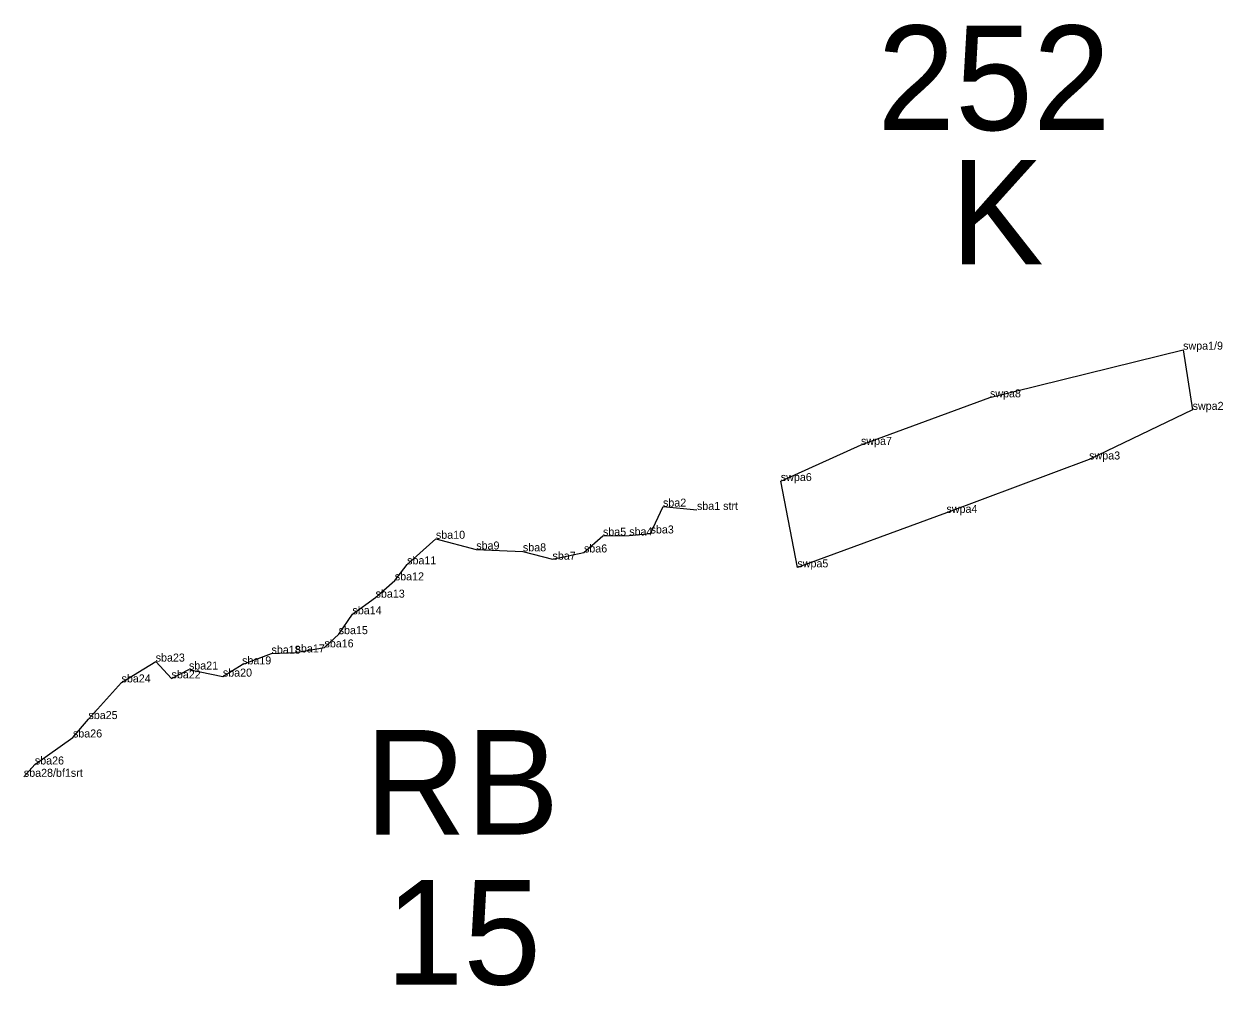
# Model space of a CAD drawing. Extents: x 2072529 to 2268796, y 436423 to 470406.
# Drawn here: x 2212483 to 2213233, y 440541 to 441142 of the extents above; entities that cross this region are included whole.
import ezdxf

# ---------------------------------------------------------------- set-up
doc = ezdxf.new("R2010")
doc.units = 0
for name, color, linetype in [('Default', 7, 'Continuous'), ('Exist Hydro Jurisdictional Stream or Body of Water NEU Mitigable', 7, 'Continuous'), ('Exist Hydro Jurisdictional Stream or Body of Water NEU Mitigable Cogo Comment', 7, 'Continuous'), ('Old_Level_20', 7, 'Continuous')]:
    doc.layers.add(name, color=color, linetype=linetype)

msp = doc.modelspace()

# ---------------------------------------------------------------- linework, layer by layer
at = {"layer": 'Exist Hydro Jurisdictional Stream or Body of Water NEU Mitigable'}
msp.add_lwpolyline([(2213207.67, 440938.67), (2213213.62, 440901.09), (2213148.99, 440870.07), (2213059.83, 440836.73), (2212966.67, 440802.64), (2212956.32, 440856.6), (2213006.42, 440879.17), (2213087, 440908.88)], close=True, dxfattribs=at)
msp.add_lwpolyline([(2212483.34, 440671.77), (2212490.22, 440679.47), (2212514.04, 440696.37), (2212523.7, 440707.85), (2212544.37, 440730.76), (2212565.72, 440743.79), (2212575.62, 440733.28), (2212586.51, 440738.8), (2212607.7, 440734.4), (2212619.7, 440742.03), (2212638.08, 440748.74), (2212653.12, 440749.49), (2212671.17, 440752.66), (2212680.06, 440760.92), (2212688.66, 440773.35), (2212703.11, 440783.75), (2212715.14, 440794.53), (2212722.83, 440804.55), (2212740.82, 440820.52), (2212766.02, 440813.82), (2212795.17, 440812.67), (2212813.67, 440807.74), (2212833.33, 440811.97), (2212845.18, 440822.43), (2212861.6, 440822.58), (2212874.93, 440823.84), (2212882.7, 440840.61), (2212903.91, 440838.55)], dxfattribs=at)
at = {"layer": 'Old_Level_20'}
for p, q in [((2213207.67, 440938.67), (2213207.67, 440938.67)), ((2213087, 440908.88), (2213087, 440908.88)), ((2213213.62, 440901.09), (2213213.62, 440901.09)), ((2213006.42, 440879.17), (2213006.42, 440879.17)), ((2213148.99, 440870.07), (2213148.99, 440870.07)), ((2212956.32, 440856.6), (2212956.32, 440856.6)), ((2212882.7, 440840.61), (2212882.7, 440840.61)), ((2212903.91, 440838.55), (2212903.91, 440838.55)), ((2213059.83, 440836.73), (2213059.83, 440836.73)), ((2212874.93, 440823.84), (2212874.93, 440823.84)), ((2212740.82, 440820.52), (2212740.82, 440820.52)), ((2212845.18, 440822.43), (2212845.18, 440822.43)), ((2212861.6, 440822.58), (2212861.6, 440822.58)), ((2212766.02, 440813.82), (2212766.02, 440813.82)), ((2212795.17, 440812.67), (2212795.17, 440812.67)), ((2212833.33, 440811.97), (2212833.33, 440811.97)), ((2212722.83, 440804.55), (2212722.83, 440804.55)), ((2212813.67, 440807.74), (2212813.67, 440807.74)), ((2212966.67, 440802.64), (2212966.67, 440802.64)), ((2212715.14, 440794.53), (2212715.14, 440794.53)), ((2212703.11, 440783.75), (2212703.11, 440783.75)), ((2212688.66, 440773.35), (2212688.66, 440773.35)), ((2212680.06, 440760.92), (2212680.06, 440760.92)), ((2212638.08, 440748.74), (2212638.08, 440748.74)), ((2212653.12, 440749.49), (2212653.12, 440749.49)), ((2212671.17, 440752.66), (2212671.17, 440752.66)), ((2212565.72, 440743.79), (2212565.72, 440743.79)), ((2212619.7, 440742.03), (2212619.7, 440742.03)), ((2212575.62, 440733.28), (2212575.62, 440733.28)), ((2212586.51, 440738.8), (2212586.51, 440738.8)), ((2212607.7, 440734.4), (2212607.7, 440734.4)), ((2212544.37, 440730.76), (2212544.37, 440730.76)), ((2212523.7, 440707.85), (2212523.7, 440707.85)), ((2212514.04, 440696.37), (2212514.04, 440696.37)), ((2212490.22, 440679.47), (2212490.22, 440679.47))]:
    msp.add_line(p, q, dxfattribs=at)

# ---------------------------------------------------------------- texts
at = {"layer": 'Default'}
for s, p in [('252', (2213016.6, 441075.9)), ('K', (2213062.27, 440991.94)), ('RB', (2212696.5, 440635.65)), ('RB', (2212696.5, 440635.65)), ('15', (2212709.35, 440541.97))]:
    msp.add_text(s, height=65.34, dxfattribs=at).set_placement(p)
at = {"layer": 'Exist Hydro Jurisdictional Stream or Body of Water NEU Mitigable Cogo Comment'}
for s, p in [('swpa1/9', (2213207.67, 440938.67)), ('swpa8', (2213087, 440908.88)), ('swpa2', (2213213.62, 440901.09)), ('swpa7', (2213006.42, 440879.17)), ('swpa3', (2213148.99, 440870.07)), ('swpa6', (2212956.32, 440856.6)), ('sba2', (2212882.7, 440840.61)), ('sba1 strt', (2212903.91, 440838.55)), ('swpa4', (2213059.83, 440836.73)), ('sba10', (2212740.82, 440820.52)), ('sba5', (2212845.18, 440822.43)), ('sba4', (2212861.6, 440822.58)), ('sba3', (2212874.93, 440823.84)), ('sba9', (2212766.02, 440813.82)), ('sba8', (2212795.17, 440812.67)), ('sba6', (2212833.33, 440811.97)), ('sba11', (2212722.83, 440804.55)), ('sba7', (2212813.65, 440807.43)), ('swpa5', (2212966.67, 440802.64)), ('sba12', (2212715.14, 440794.53)), ('sba13', (2212703.11, 440783.75)), ('sba14', (2212688.66, 440773.35)), ('sba15', (2212680.06, 440760.92)), ('sba16', (2212671.17, 440752.66)), ('sba23', (2212565.72, 440743.79)), ('sba18', (2212638.08, 440748.74)), ('sba17', (2212653.12, 440749.49)), ('sba21', (2212586.51, 440738.8)), ('sba19', (2212619.7, 440742.03)), ('sba24', (2212544.37, 440730.76)), ('sba22', (2212575.62, 440733.28)), ('sba20', (2212607.7, 440734.4)), ('sba25', (2212523.7, 440707.85)), ('sba26', (2212514.04, 440696.37)), ('sba26', (2212490.22, 440679.47)), ('sba28/bf1srt', (2212483.34, 440671.77))]:
    msp.add_text(s, height=5, dxfattribs=at).set_placement(p)

doc.saveas('drawing.dxf')
